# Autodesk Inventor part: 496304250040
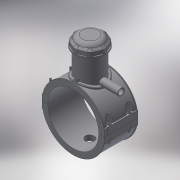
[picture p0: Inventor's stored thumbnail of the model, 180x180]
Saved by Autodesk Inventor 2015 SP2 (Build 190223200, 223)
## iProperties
Created: 2017-07
Part Number: 496304250040
Material: Generic
Description: PLASSON TAPPING SADDLE 250x40
Document SubType Name: Modeling
Designer: KIM
Mass: 1972.1 g
Surface Area: 3874.95 cm^2
Volume: 1972.1 cm^3
Density: 1 g/cm^3
Appearance: Default
Author: KIM
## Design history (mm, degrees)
derived "496304.ipt"
feature "Solid1::496304.ipt"
feature "Solid2::496304.ipt"
feature "Solid4::496304.ipt"
feature "Solid5::496304.ipt"
tag "TaggingFeature1" dims "d2" = 327.6
body "Solid1"
body "Solid2"
other parameters: "d3" = 62.5, "d4" = 176, "d5" = 0, "d6" = 0.1, "d8" = 0, "d19" = 6, "d20" = 6, "d21" = 105.6, "d23" = 0, "d24" = 52.8, "d26" = 0, "d29" = 3, "d30" = 83.33333, "d31" = 6, "d32" = 0, "d33" = 0, "d34" = 0.6, "d40" = 148.2, "d43" = 0, "d45" = 0, "d47" = 248.1, "d70" = 15, "d72" = 0, "d73" = 6, "d75" = 5, "d76" = 0, "d77" = 12.5, "d78" = 155, "d79" = 15, "d80" = 70.4, "d82" = 5 deg, "d84" = 4, "d85" = 14, "d86" = 0, "d87" = 3, "d88" = 0, "d89" = 1, "d90" = 1, "d91" = 140.8, "d92" = 0, "d93" = 0.5, "d94" = 131.57895, "d96" = 290.7, "d97" = 3.52, "d98" = 0, "d102" = 2.5, "d120" = 140 deg, "d121" = 24.228, "d122" = 20 deg, "d124" = 171, "d126" = 0, "d143" = 257.5, "d145" = 26.92308, "d149" = 3.75, "d150" = 29.61538, "d153" = 176, "d154" = 0, "d156" = 142.5, "d157" = 160 deg, "d159" = 7, "d161" = 3.75, "d162" = 105.6, "d163" = 0, "d164" = 125, "d167" = 25, "d168" = 139.02439, "d170" = 3.75, "d172" = 0, "d173" = 1, "d175" = 125, "d176" = 20 deg, "d177" = 17.5, "d178" = 35, "d180" = 0, "d183" = 14, "d184" = 14, "d185" = 57.2, "d186" = 57.2, "d187" = 142.5, "d188" = 10.5, "d189" = 17.5, "d190" = 0, "d191" = 213.75, "d193" = 7, "d194" = 6.16, "d195" = 90 deg, "d197" = 0, "d199" = 0, "d200" = 17.5, "d202" = 0, "d203" = 177, "d204" = 95, "d206" = 85, "d207" = 132.75, "d208" = 138.06, "d209" = 164.61, "d210" = 86, "d213" = 36, "d216" = 0, "d217" = 25, "d218" = 25, "d219" = 5, "d224" = 0, "d230" = 5, "d233" = 6, "d236" = 126, "d237" = 52.8, "d238" = 6.02433, "d240" = 52.8, "d241" = 52.8, "d242" = 52.8, "d243" = 6, "d244" = 52.8, "d245" = 52.8, "d246" = 52.8, "d247" = 6, "d248" = 6, "d249" = 6, "d251" = 52.8, "d253" = 6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
